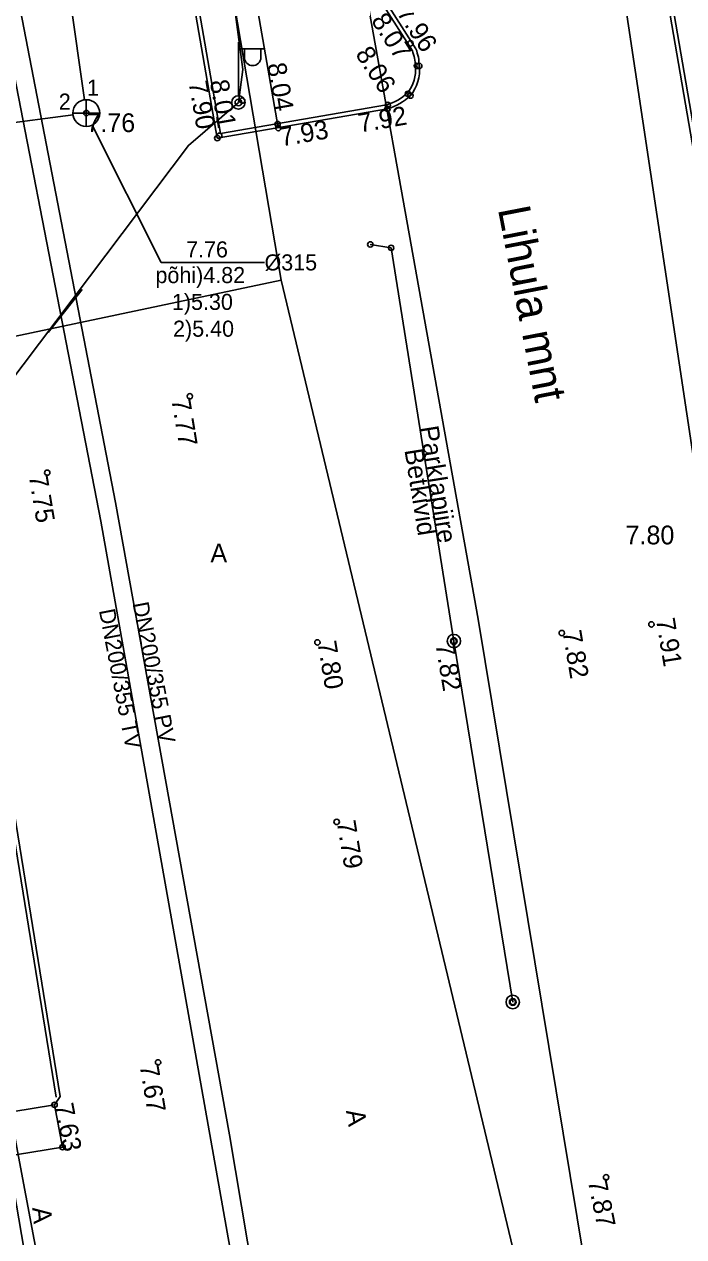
# Model space of a CAD drawing. Extents: x 473307 to 473719, y 6532843 to 6533381.
# Drawn here: x 473609.21 to 473633.83, y 6533134.94 to 6533180.18 of the extents above; entities that cross this region are included whole.
import ezdxf

# ---------------------------------------------------------------- set-up
doc = ezdxf.new("R2010")
doc.units = 0
for name, color, linetype in [('Default', 7, 'Continuous'), ('KORGUS', 7, 'Continuous'), ('KPKAABEL', 7, 'Continuous'), ('LIIKLUS', 7, 'Continuous'), ('MPKAABEL', 7, 'Continuous'), ('PIIR', 7, 'Continuous'), ('POST', 7, 'Continuous'), ('SITRASS', 7, 'Continuous'), ('SKKAEV', 7, 'Continuous'), ('SKKAEV_NR', 7, 'Continuous'), ('SKTRASS', 7, 'Continuous'), ('TEE', 7, 'Continuous'), ('TTRASS', 7, 'Continuous'), ('TTRASS_TEKST', 7, 'Continuous'), ('VTRASS', 7, 'Continuous')]:
    doc.layers.add(name, color=color, linetype=linetype)

# ---------------------------------------------------------------- blocks, each defined once
blk = doc.blocks.new('KAKAEV')
at = {"layer": 'Default'}
for p, q in [((0, -1), (0, 1)), ((-1, 0), (1, 0))]:
    blk.add_line(p, q, dxfattribs=at)
blk.add_circle((0, 0), 1, dxfattribs=at)
blk = doc.blocks.new('MEPOST')
at = {"layer": 'Default'}
blk.add_circle((0, 0), 0.5, dxfattribs=at)
for start, end in [(0, 180), (180, 0)]:
    blk.add_arc((0, 0), 0.25, start, end, dxfattribs=at)
blk = doc.blocks.new('VAPOST')
at = {"layer": 'Default'}
for p, q in [((0, 0.5), (0, 4.5)), ((0, 4), (2, 4)), ((0.453, 3.358), (0.453, 4)), ((1.679, 3.358), (1.679, 4))]:
    blk.add_line(p, q, dxfattribs=at)
blk.add_arc((1.066, 3.358), 0.613, 180, 0, dxfattribs=at)

msp = doc.modelspace()

# ---------------------------------------------------------------- linework, layer by layer
at = {"layer": 'KORGUS'}
for centre in [(473623.63, 6533179.471), (473623.871, 6533178.628), (473623.958, 6533178.629), (473617.352, 6533177.336), (473623.531, 6533177.588), (473623.628, 6533177.52), (473611.53, 6533176.869), (473622.771, 6533177.029), (473622.784, 6533177.171), (473618.668, 6533176.458), (473616.417, 6533175.935), (473616.491, 6533176.024), (473618.697, 6533176.313), (473622.129, 6533171.967), (473622.907, 6533171.841), (473615.393, 6533166.3), (473610.07, 6533163.449), (473629.276, 6533157.467), (473632.621, 6533157.79), (473620.155, 6533157.118), (473625.247, 6533157.167), (473620.874, 6533150.419), (473627.445, 6533143.697), (473614.208, 6533141.445), (473610.344, 6533139.861), (473610.643, 6533138.281), (473630.93, 6533137.158)]:
    msp.add_circle(centre, 0.1, dxfattribs=at)
at = {"layer": 'KPKAABEL'}
msp.add_lwpolyline([(473575.894, 6533057.765), (473578.381, 6533058.268), (473592.823, 6533060.715), (473621.311, 6533065.257), (473623.181, 6533065.813), (473626.204, 6533066.359), (473627.317, 6533067.271), (473626.267, 6533076.719), (473623.676, 6533096.66), (473614.05, 6533106.128), (473613.895, 6533110.57), (473612.665, 6533115.488), (473610.79, 6533128.403), (473608.964, 6533138.127), (473603.611, 6533167.485), (473599.245, 6533215.151)], dxfattribs=at)
at = {"layer": 'LIIKLUS'}
msp.add_lwpolyline([(473627.445, 6533143.697), (473625.247, 6533157.167), (473622.907, 6533171.841), (473622.129, 6533171.967)], dxfattribs=at)
at = {"layer": 'MPKAABEL'}
for points in [[(473612.486, 6533203.753), (473615.782, 6533190.445), (473617.366, 6533178.496), (473617.205, 6533177.267)], [(473615.782, 6533190.445), (473617.366, 6533178.496), (473617.205, 6533177.267), (473615.341, 6533175.66), (473607.296, 6533164.994), (473606.71, 6533163.582), (473605.869, 6533161.459), (473606.18, 6533152.225), (473608.02, 6533151.39), (473606.563, 6533149.914), (473609.293, 6533133.925), (473612.181, 6533121.451), (473612.877, 6533120.17), (473613.933, 6533119.264), (473620.684, 6533114.954), (473633.022, 6533109.833)], [(473617.205, 6533177.267), (473615.341, 6533175.66), (473607.296, 6533164.994), (473606.71, 6533163.582), (473605.869, 6533161.459), (473606.18, 6533152.225), (473608.02, 6533151.39)], [(473611.375, 6533170.289), (473610.103, 6533168.686)]]:
    msp.add_lwpolyline(points, dxfattribs=at)
at = {"layer": 'PIIR'}
msp.add_lwpolyline([(473678.608, 6532842.593), (473677.66, 6532847.73), (473668.24, 6532906.4), (473664.64, 6532927.81), (473654.16, 6532926.37), (473630.89, 6533065.72), (473641.36, 6533067.51), (473636.3, 6533097.55), (473618.8, 6533170.64), (473609.94, 6533222.84), (473601.54, 6533272.81), (473599.09, 6533295.91), (473592.3, 6533328.43), (473587.14, 6533353.72), (473584.47, 6533353.28), (473580.56, 6533374.06), (473585.23, 6533374.14), (473584.699, 6533380.885)], dxfattribs=at)
for points in [[(473558.63, 6533220.73), (473567.96, 6533221.17), (473586.39, 6533221.76), (473609.94, 6533222.84), (473618.8, 6533170.64), (473601.75, 6533167.04), (473561.43, 6533165.2), (473559.2, 6533209.37)], [(473607.56, 6533132.38), (473601.75, 6533167.04), (473618.8, 6533170.64), (473636.3, 6533097.55), (473641.36, 6533067.51), (473630.89, 6533065.72), (473618.6, 6533063.82), (473611.09, 6533109.85)]]:
    msp.add_lwpolyline(points, close=True, dxfattribs=at)
at = {"layer": 'SITRASS'}
msp.add_lwpolyline([(473619.744, 6533193.777), (473626.15, 6533157.979), (473633.016, 6533116.458)], dxfattribs=at)
at = {"layer": 'SKKAEV_NR'}
msp.add_lwpolyline([(473611.754, 6533176.423), (473614.326, 6533171.297), (473618.181, 6533171.297)], dxfattribs=at)
at = {"layer": 'SKTRASS'}
for p, q in [((473605.197, 6533221.962), (473611.461, 6533177.365)), ((473602.918, 6533175.754), (473611.034, 6533176.805))]:
    msp.add_line(p, q, dxfattribs=at)
at = {"layer": 'TEE'}
for points in [[(473616.846, 6533218.552), (473615.311, 6533211.969), (473616.217, 6533206.716), (473618.71, 6533192.337), (473619.951, 6533185.079), (473623.699, 6533179.197)], [(473616.994, 6533218.524), (473615.464, 6533211.964), (473616.365, 6533206.742), (473618.858, 6533192.362), (473620.094, 6533185.134), (473623.834, 6533179.264)], [(473604.729, 6533213.816), (473611.931, 6533215.063), (473614.566, 6533199.957), (473614.566, 6533199.957), (473615.517, 6533194.507), (473615.909, 6533192.334), (473618.695, 6533176.327)], [(473622.771, 6533177.029), (473616.417, 6533175.935), (473613.178, 6533194.593), (473610.621, 6533209.151)], [(473622.737, 6533177.176), (473616.539, 6533176.108), (473613.326, 6533194.619), (473610.795, 6533209.029)], [(473644.295, 6533115.383), (473644.06, 6533116.857), (473637.205, 6533157.979), (473637.169, 6533158.224), (473632.312, 6533186.387)], [(473644.443, 6533115.407), (473644.208, 6533116.882), (473637.353, 6533158.002), (473637.317, 6533158.248), (473632.46, 6533186.412)], [(473602.033, 6533164.132), (473606.506, 6533164.813), (473608.561, 6533152.474), (473610.558, 6533140.166)], [(473602.056, 6533163.984), (473606.382, 6533164.642), (473608.413, 6533152.45), (473610.41, 6533140.14)], [(473606.387, 6533139.208), (473610.344, 6533139.861), (473610.643, 6533138.281), (473606.663, 6533137.638)], [(473610.344, 6533139.861), (473610.558, 6533140.166)]]:
    msp.add_lwpolyline(points, dxfattribs=at)
for centre, radius, start, end in [((473621.951, 6533178.567), 1.858, 1.6136, 19.8427), ((473621.951, 6533178.567), 2.008, 1.7846, 20.3266), ((473622.457, 6533178.472), 1.359, 321.289, 6.2196), ((473622.457, 6533178.472), 1.509, 320.8905, 5.989), ((473622.203, 6533179.015), 1.915, 286.1904, 313.3415), ((473622.203, 6533179.015), 2.065, 285.9526, 313.6284)]:
    msp.add_arc(centre, radius, start, end, dxfattribs=at)
at = {"layer": 'TTRASS'}
for points in [[(473591.775, 6533277.426), (473595.59, 6533253.766), (473601.028, 6533223.219), (473603.147, 6533210.812), (473606.172, 6533192.662), (473606.51, 6533190.705), (473602.77, 6533190.028), (473603.588, 6533185.543), (473607.3, 6533186.208), (473612.067, 6533161.644), (473616.282, 6533137.983), (473619.426, 6533120.252), (473619.546, 6533119.497)], [(473592.297, 6533277.757), (473596.188, 6533254.087), (473601.84, 6533222.521), (473604, 6533210.082), (473607.02, 6533191.72), (473607.264, 6533190.194), (473603.552, 6533189.561), (473604.136, 6533186.261), (473607.868, 6533186.888), (473612.623, 6533162.34), (473616.873, 6533138.735), (473619.773, 6533121.514), (473620.151, 6533119.324)]]:
    msp.add_lwpolyline(points, dxfattribs=at)
at = {"layer": 'VTRASS'}
msp.add_lwpolyline([(473610.467, 6533298.54), (473612.816, 6533284.928), (473621.946, 6533241.242), (473627.014, 6533212.114), (473627.084, 6533211.254), (473634.761, 6533160.18), (473647.035, 6533084.422), (473650.297, 6533065.838)], dxfattribs=at)

# ---------------------------------------------------------------- block references
at = {"layer": 'LIIKLUS', "xscale": 0.5, "yscale": 0.5}
for p in [(473625.247, 6533157.167), (473627.445, 6533143.697)]:
    msp.add_blockref('MEPOST', p, dxfattribs=at)
at = {"layer": 'POST', "xscale": 0.5, "yscale": 0.5}
for name in ['VAPOST', 'MEPOST']:
    msp.add_blockref(name, (473617.205, 6533177.267), dxfattribs=at)
at = {"layer": 'SKKAEV', "xscale": 0.5, "yscale": 0.5}
msp.add_blockref('KAKAEV', (473611.53, 6533176.869), dxfattribs=at)

# ---------------------------------------------------------------- texts
at = {"layer": 'KORGUS'}
for s, rotation, p in [('8.07', 302.5028, (473622.14, 6533180.325)), ('7.96', 302.5028, (473623.1, 6533180.613)), ('8.06', 303, (473621.549, 6533179.072)), ('8.04', 279.8745, (473618.279, 6533178.691)), ('7.90', 279.8474, (473615.345, 6533178.016)), ('8.01', 279.8474, (473616.138, 6533178.06)), ('7.92', 9.771, (473621.74, 6533176.141)), ('7.93', 9.771, (473618.816, 6533175.623)), ('7.77', 279.457, (473614.702, 6533166.185)), ('7.75', 279.457, (473609.379, 6533163.334)), ('7.91', 279.3221, (473632.79, 6533157.973)), ('7.82', 279.4698, (473629.303, 6533157.518)), ('7.80', 279.457, (473620.155, 6533157.118)), ('7.82', 279.4505, (473624.557, 6533157.052)), ('7.79', 279.457, (473620.874, 6533150.419)), ('7.67', 279.457, (473613.517, 6533141.33)), ('7.63', 280.7214, (473610.344, 6533139.861)), ('7.87', 281.5566, (473630.244, 6533137.018))]:
    msp.add_text(s, height=0.7, rotation=rotation, dxfattribs=at).set_placement(p)
for s, p in [('7.76', (473611.532, 6533176.16)), ('7.80', (473631.655, 6533160.775))]:
    msp.add_text(s, height=0.7, dxfattribs=at).set_placement(p)
at = {"layer": 'LIIKLUS'}
for s, p in [('Parklapiire', (473623.974, 6533165.148)), ('Betkivid', (473623.401, 6533164.297))]:
    msp.add_text(s, height=0.7, rotation=279.0604, dxfattribs=at).set_placement(p)
at = {"layer": 'SKKAEV_NR'}
for s, p in [('1', (473611.553, 6533177.519)), ('2', (473610.502, 6533176.997)), ('7.76', (473615.253, 6533171.483)), ('%%c315', (473618.181, 6533170.997)), ('põhi)4.82', (473614.111, 6533170.524)), ('1)5.30', (473614.725, 6533169.524)), ('2)5.40', (473614.768, 6533168.524))]:
    msp.add_text(s, height=0.6, dxfattribs=at).set_placement(p)
at = {"layer": 'TEE'}
for s, height, rotation, p in [('Lihula mnt', 1.2, 280.9738, (473626.888, 6533173.292)), ('A', 0.7, 279.4431, (473621.218, 6533139.638)), ('A', 0.7, 275.6622, (473609.509, 6533136.022))]:
    msp.add_text(s, height=height, rotation=rotation, dxfattribs=at).set_placement(p)
msp.add_text('A', height=0.7, dxfattribs=at).set_placement((473616.163, 6533160.103))
at = {"layer": 'TTRASS_TEKST'}
for s, p in [('DN200/355 PV', (473613.254, 6533158.57)), ('DN200/355 TV', (473611.998, 6533158.311))]:
    msp.add_text(s, height=0.6, rotation=280.9722, dxfattribs=at).set_placement(p)

doc.saveas('drawing.dxf')
